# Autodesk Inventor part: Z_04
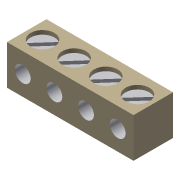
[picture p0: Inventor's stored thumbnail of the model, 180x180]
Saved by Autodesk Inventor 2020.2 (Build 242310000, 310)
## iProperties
GlobalPropertyList: <PropertyList/>
Manager: www.cadconsulting.pl
Company: Fabian Stasiak CAD Consulting
Created: 2014-09
Part Number: Z_04
Material: Ogólny
Document SubType Name: Modeling
Designer: F.Stasiak
Density: 1 g/cm^3
Appearance: Beżowa
Categories: <MemberInstance><Categories><Category DisplayName="" Mnemonic="CABLEANDHARNESS" InternalName="e4a7e005-5e42-4d16-b293-125e7f0d0512"><Category DisplayName="" Mne
Catalog Web Link: www.expertbooks.pl
Author: F.Stasiak
Subject: Zbiór ćwiczeń. Autodesk Inventor 2020. Kurs Professional
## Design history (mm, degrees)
sketch "Szkic1"
  geometry: L1 (-8, 2.5)-(8, 2.5); L2 (8, 2.5)-(8, -2.5); L3 (8, -2.5)-(-8, -2.5); L4 (-8, -2.5)-(-8, 2.5); L5 (-8, 2.5)-(8, -2.5); L6 (8, 2.5)-(-8, -2.5); 1 further point
  constraints: 12 end point, 2 midpoint, 2 parallel, 1 horizontal, 1 perpendicular
  dimensions: "d0" = 16 distance of L2.end L3.end; "d1" = 5 distance of L1.end L2.end
extrude "Wyciągnięcie proste1" new body sketch "Szkic1" distance "d2" = 5; taper "d3" = 0 deg
sketch "Szkic2"
  geometry: L1 (16, 0)-(0, 0) reference; L2 (16, 0)-(16, 5) reference; L3 (6, 2.5)-(10, 2.5); L4 (0, 0)-(0, 5) reference; C1 r 1 at (6, 2.5); C2 r 1 at (10, 2.5); C3 r 1 at (2, 2.5); C4 r 1 at (14, 2.5); 5 further points
  constraints: 5 midpoint, 4 centre point, 3 horizontal alignment, 2 end point, 2 equal radius, 1 horizontal, 1 vertical alignment
  dimensions: "d5" = 2 diameter of C1; "d6" = 2 diameter of C2; "d7" = 4 distance of L3.start L3.end; "d19" = 4 distance of L3.start C3.centre (= d7); "d20" = 4 distance of C4.centre L3.end (= d7)
extrude "Wyciągnięcie proste2" cut sketch "Szkic2" distance "d8" = 4; taper "d9" = 0 deg
sketch "Szkic3"
  geometry: L1 (-2, 0)-(2, 0); L2 (-8, 2.5)-(-8, -2.5) reference; L3 (8, -2.5)-(8, 2.5) reference; C1 r 1.5 at (-2, 0); C2 r 1.5 at (2, 0); C3 r 1.5 at (-6, 0); C4 r 1.5 at (6, 0); 4 further points
  constraints: 4 centre point, 3 midpoint, 2 end point, 2 equal radius, 2 horizontal alignment, 1 coincident, 1 horizontal
  dimensions: "d10" = 3 diameter of C1; "d11" = 3 diameter of C2; "d12" = 4 distance of L1.start L1.end; "d21" = 4 distance of L1.start C3.centre (= d12); "d22" = 4 distance of C4.centre L1.end (= d12)
extrude "Wyciągnięcie proste3" cut sketch "Szkic3" distance "d13" = 0.5; taper "d14" = 0 deg
sketch "Szkic4"
  geometry: L1 (-1, -1.118)-(1, 1.118); L2 (1, -2.5)-(1, 1.5) reference; L3 (-1.188, -0.916)-(0.778, 1.282); L4 (-0.778, -1.282)-(1.188, 0.916); L5 (3, -1.118)-(5, 1.118); L6 (-0.205, 0.183)-(0.205, -0.183); L7 (3.795, 0.183)-(4.205, -0.183); L8 (2.812, -0.916)-(4.778, 1.282); L9 (3.222, -1.282)-(5.188, 0.916); L10 (-5.188, -0.916)-(-3.222, 1.282); L11 (-4.778, -1.282)-(-2.812, 0.916); L12 (6.812, -0.916)-(8.778, 1.282); L13 (7.222, -1.282)-(9.188, 0.916); L14 (-4.205, 0.183)-(-3.795, -0.183); L15 (7.795, 0.183)-(8.205, -0.183); A1 r 1.5 centre (0, 0) between (-1, -1.118) and (1, 1.118) reference; A2 r 1.5 centre (4, 0) between (3, -1.118) and (5, 1.118) reference; A3 r 1.5 centre (4, 0) between (3, -1.118) and (5, 1.118) reference; A4 r 1.5 centre (-4, 0) between (-5.188, -0.916) and (-3.222, 1.282) reference; A5 r 1.5 centre (8, 0) between (6.812, -0.916) and (8.778, 1.282) reference; A6 r 1.5 centre (8, 0) between (7.222, -1.282) and (9.188, 0.916) reference; 6 further points
  constraints: 28 end point, 28 point on circle, 14 midpoint, 11 parallel, 4 coincident, 1 point on line, 2 other
  dimensions: "d15" = 0.55 distance between parallel lines of L3 L4
extrude "Wyciągnięcie proste4" cut sketch "Szkic4" distance "d17" = 0.5; taper "d18" = 0 deg
node "Bryła1"
node "Pętla rzutowana1"
node "Pętla rzutowana2"
node "Pętla rzutowana3"
node "Pętla rzutowana4"
